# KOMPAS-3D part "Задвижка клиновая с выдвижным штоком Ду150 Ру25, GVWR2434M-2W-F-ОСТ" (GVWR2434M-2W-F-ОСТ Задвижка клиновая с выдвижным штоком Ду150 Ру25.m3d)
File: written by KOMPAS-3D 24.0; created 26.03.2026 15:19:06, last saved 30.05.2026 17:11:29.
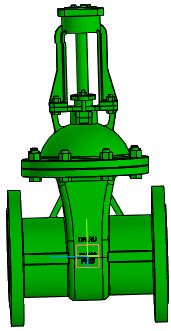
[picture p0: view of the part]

Document properties: Автор: R2D2; Полное имя файла: E:\Работа\Зайцев\GVWR2434M-2W-F-ОСТ Задвижка клиновая с выдвижным штоком DN.ru Ду50-300 Ру25\исходные материалы\DN150\DN150\GVWR2434M-2W-F-ОСТ Задвижка клиновая с выдвижным штоком Ду150 Ру25.m3d

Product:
- Part/product: Задвижка клиновая с выдвижным штоком Ду150 Ру25  | designation GVWR2434M-2W-F-ОСТ
    Масса: 60
    Раздел спецификации: Прочие изделия
    Примечание: D040-07589
    additional columns: D040-10013

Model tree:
1. Операция без истории:1

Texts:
  GVWR2434M-2W-F-ОСТ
